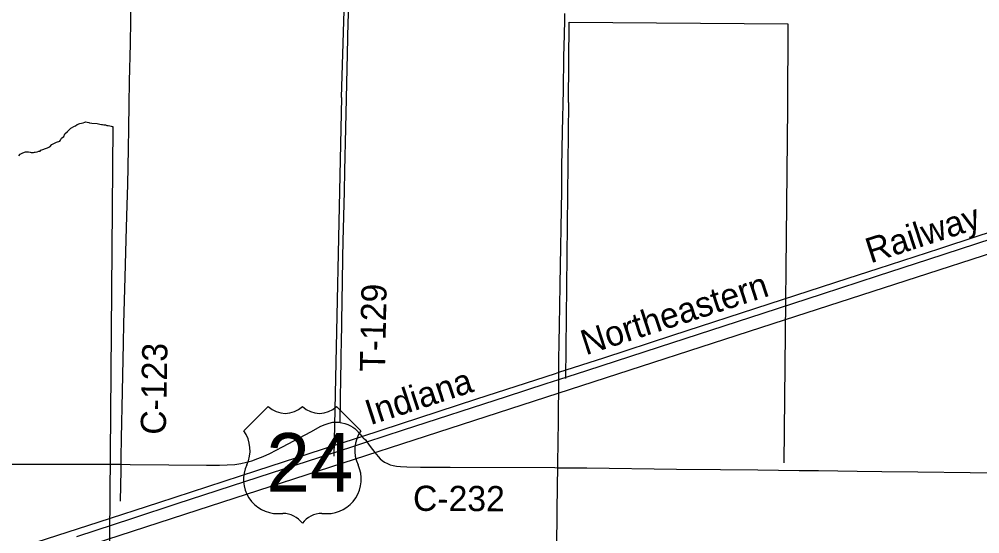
# Model space of a CAD drawing. Extents: x 2.1 to 73.9, y 4 to 26.
# Drawn here: x 44.489 to 45.571, y 21.257 to 21.837 of the extents above; entities that cross this region are included whole.
import ezdxf

# ---------------------------------------------------------------- set-up
doc = ezdxf.new("R2010")
doc.units = 0
for name, color, linetype in [('GM_X_County_Road', 7, 'Continuous'), ('GM_X_County_Road_Text', 7, 'Continuous'), ('GM_X_Minor_River', 7, 'Continuous'), ('GM_X_Rail_Line', 7, 'Continuous'), ('GM_X_Rail_Line_Text', 7, 'Continuous'), ('GM_X_Township_Road', 7, 'Continuous'), ('GM_X_Township_Road_Text', 7, 'Continuous'), ('GM_X_US_Location', 7, 'Continuous'), ('GM_X_US_Route', 7, 'Continuous'), ('GM_X_US_Shield', 7, 'Continuous')]:
    doc.layers.add(name, color=color, linetype=linetype)

msp = doc.modelspace()

# ---------------------------------------------------------------- linework, layer by layer
at = {"layer": 'GM_X_County_Road'}
for points in [[(44.6036, 21.3349), (44.6037, 21.3424), (44.604, 21.3642), (44.6051, 21.417), (44.6063, 21.4714), (44.6067, 21.4932), (44.6079, 21.546), (44.6088, 21.574), (44.6094, 21.602), (44.6102, 21.6269), (44.6109, 21.6502), (44.6119, 21.6906), (44.6122, 21.7139), (44.6125, 21.7404), (44.6131, 21.7668), (44.614, 21.8088), (44.6143, 21.8352), (44.6146, 21.8461), (44.6146, 21.8484)], [(45.0966, 21.4305), (45.0966, 21.432), (45.0967, 21.4386), (45.0968, 21.4538), (45.0971, 21.4709), (45.0975, 21.4926), (45.0978, 21.5128), (45.0981, 21.5377), (45.1, 21.6434), (45.1002, 21.6698), (45.101, 21.7102), (45.1018, 21.7568), (45.1025, 21.7941), (45.1031, 21.819), (45.1033, 21.836), (45.1033, 21.8392), (45.1033, 21.843)], [(45.0955, 21.331), (45.0956, 21.3357), (45.0963, 21.3839), (45.0964, 21.401), (45.0966, 21.4134), (45.0966, 21.4211), (45.0966, 21.4305)], [(44.6036, 21.3349), (44.6136, 21.3348), (44.6571, 21.3344), (44.6997, 21.3339), (44.7038, 21.3338), (44.7144, 21.3338), (44.7228, 21.3341), (44.7315, 21.3348), (44.7383, 21.3358), (44.7447, 21.3372), (44.7507, 21.3389), (44.7575, 21.3413), (44.7635, 21.3438), (44.7709, 21.3472), (44.7852, 21.3547), (44.8171, 21.3716), (44.8286, 21.3777), (44.8334, 21.3799), (44.8378, 21.3814), (44.842, 21.3822), (44.8456, 21.3824), (44.849, 21.3823), (44.8504, 21.3821)], [(44.8504, 21.3821), (44.8523, 21.3818), (44.8556, 21.381), (44.8591, 21.3798), (44.8621, 21.3784), (44.8647, 21.3768), (44.8669, 21.3751), (44.8684, 21.3736), (44.8727, 21.3687), (44.8738, 21.3675), (44.8748, 21.3663)], [(44.8748, 21.3663), (44.8763, 21.3648), (44.8787, 21.3624), (44.8802, 21.3605), (44.8805, 21.3601), (44.8842, 21.355), (44.8892, 21.3482), (44.893, 21.3436), (44.8954, 21.3411), (44.8978, 21.3391), (44.9004, 21.3373), (44.9035, 21.3357), (44.9067, 21.3344), (44.91, 21.3334), (44.9137, 21.3327), (44.9181, 21.3322), (44.9256, 21.3319), (44.9408, 21.3316), (44.9742, 21.3315), (45.0923, 21.3311), (45.0955, 21.331)], [(44.1039, 21.3377), (44.1441, 21.3374), (44.169, 21.3371), (44.183, 21.3371), (44.2094, 21.3368), (44.2778, 21.3362), (44.3073, 21.3361), (44.3851, 21.3355), (44.4146, 21.3354), (44.4581, 21.3352), (44.4799, 21.3352), (44.5561, 21.3351), (44.5996, 21.335), (44.6036, 21.3349)], [(45.0892, 20.8284), (45.0892, 20.8291), (45.0898, 20.8539), (45.0904, 20.8943), (45.0908, 20.9285), (45.0915, 20.9751), (45.0919, 21.014), (45.0926, 21.0917), (45.0928, 21.1212), (45.0932, 21.157), (45.094, 21.2129), (45.0944, 21.2409), (45.0948, 21.2813), (45.0951, 21.3108), (45.0955, 21.331)], [(45.0955, 21.331), (45.1281, 21.3308), (45.2291, 21.3295), (45.2789, 21.329), (45.3208, 21.3286), (45.3674, 21.3279), (45.3892, 21.3277), (45.4327, 21.3272), (45.4607, 21.3269), (45.5011, 21.3264), (45.5602, 21.3257), (45.6027, 21.3251)]]:
    msp.add_lwpolyline(points, dxfattribs=at)
at = {"layer": 'GM_X_Minor_River'}
for points in [[(44.8519, 21.7485), (44.8549, 21.8464)], [(45.1074, 21.7427), (45.1083, 21.8335), (45.3549, 21.8315), (45.3543, 21.737)], [(44.8519, 21.7485), (44.8432, 21.3439)], [(45.1074, 21.7427), (45.1041, 21.4317)], [(45.3543, 21.737), (45.3501, 21.3367)], [(44.4883, 21.6826), (44.4897, 21.6847), (44.4927, 21.6861), (44.4958, 21.6872), (44.4975, 21.6873), (44.4992, 21.6871), (44.5009, 21.6869), (44.5022, 21.6865), (44.5034, 21.6864), (44.5047, 21.6864), (44.5059, 21.6866), (44.5068, 21.6867), (44.5087, 21.6873), (44.5108, 21.6878), (44.5122, 21.6879), (44.513, 21.6891), (44.5204, 21.6917), (44.5221, 21.6923), (44.5231, 21.6928), (44.5255, 21.6954), (44.5306, 21.6982), (44.5343, 21.699), (44.5353, 21.7003), (44.5364, 21.7026), (44.5388, 21.7043), (44.5402, 21.7073), (44.5431, 21.7102), (44.5468, 21.7138), (44.551, 21.7161), (44.5522, 21.7163), (44.5539, 21.718), (44.557, 21.7192), (44.5606, 21.7199), (44.5625, 21.7206), (44.5637, 21.7208), (44.5654, 21.7206)], [(44.5654, 21.7206), (44.5671, 21.7203), (44.568, 21.7199), (44.5705, 21.7195), (44.5764, 21.719), (44.5781, 21.7186), (44.5796, 21.7183), (44.5813, 21.7181), (44.5826, 21.7179), (44.5839, 21.7177), (44.586, 21.7174), (44.5875, 21.717), (44.589, 21.7168), (44.5906, 21.7164), (44.5921, 21.7162), (44.5934, 21.7158), (44.5943, 21.7157)], [(44.5943, 21.7157), (44.5872, 20.8842)]]:
    msp.add_lwpolyline(points, dxfattribs=at)
at = {"layer": 'GM_X_Rail_Line'}
msp.add_lwpolyline([(41.9585, 20.391), (42.5865, 20.5973), (42.8825, 20.6932), (43.1284, 20.7728), (43.6337, 20.9392), (44.1637, 21.1124), (44.7042, 21.288), (45.0958, 21.4151), (45.351, 21.4977), (46.1224, 21.7471), (46.3771, 21.8296)], dxfattribs=at)
at = {"layer": 'GM_X_Township_Road'}
for points in [[(44.8504, 21.3821), (44.8504, 21.3871), (44.8506, 21.4049), (44.851, 21.4359), (44.8513, 21.4468), (44.8516, 21.4608), (44.8517, 21.4701), (44.8526, 21.5198), (44.853, 21.54), (44.8533, 21.5679), (44.8537, 21.5866), (44.8551, 21.6424), (44.8555, 21.6657), (44.8566, 21.7139), (44.8584, 21.7977), (44.8593, 21.8334), (44.8596, 21.8412), (44.8598, 21.8447)], [(44.6028, 21.2932), (44.6036, 21.3284), (44.6036, 21.3349)]]:
    msp.add_lwpolyline(points, dxfattribs=at)
at = {"layer": 'GM_X_US_Route'}
for points in [[(44.5079, 21.2469), (44.5788, 21.2699), (44.6459, 21.2917), (44.7565, 21.3277), (44.8454, 21.3567), (44.8748, 21.3663), (45.0044, 21.4085), (45.0931, 21.4374), (45.0967, 21.4386), (45.1475, 21.455), (45.2253, 21.4804), (45.3338, 21.5156), (45.4227, 21.5446), (45.4564, 21.5556), (45.5259, 21.5782), (45.5681, 21.592), (45.6107, 21.6058)], [(44.5535, 21.2536), (44.6165, 21.2741), (44.6667, 21.2905), (44.758, 21.3202), (44.8009, 21.3342), (44.8633, 21.3545), (44.8805, 21.3601), (44.9218, 21.3736), (45.0379, 21.4114), (45.0826, 21.4259), (45.0966, 21.4305), (45.1284, 21.4408), (45.21, 21.4673), (45.327, 21.5054), (45.3938, 21.5271), (45.4556, 21.5473), (45.5135, 21.5662), (45.6563, 21.6126)]]:
    msp.add_lwpolyline(points, dxfattribs=at)
at = {"layer": 'GM_X_US_Shield'}
for p, q in [((44.7693, 21.4002), (44.7418, 21.3727)), ((44.8737, 21.3727), (44.8462, 21.4002)), ((44.7803, 21.2793), (44.7858, 21.2793)), ((44.8297, 21.2793), (44.8352, 21.2793))]:
    msp.add_line(p, q, dxfattribs=at)
for centre, radius, start, end in [((44.7885, 21.4198), 0.0275, 225.573, 314.427), ((44.827, 21.4198), 0.0275, 225.573, 314.427), ((44.7103, 21.3507), 0.0385, 334.5471, 35.0009), ((44.9052, 21.3507), 0.0385, 144.9991, 205.4529), ((44.7798, 21.3178), 0.0385, 154.8319, 270.6383), ((44.8356, 21.3178), 0.0385, 269.3617, 25.1681), ((44.7858, 21.2519), 0.0275, 36.8699, 90), ((44.8297, 21.2519), 0.0275, 90, 143.1301)]:
    msp.add_arc(centre, radius, start, end, dxfattribs=at)

# ---------------------------------------------------------------- texts
at = {"layer": 'GM_X_County_Road_Text'}
for s, rotation, p in [('C-123', 88.8986, (44.6538, 21.368)), ('C-232', 359.7253, (44.9323, 21.2824))]:
    msp.add_text(s, height=0.02841, rotation=rotation, dxfattribs=at).set_placement(p)
at = {"layer": 'GM_X_Rail_Line_Text'}
for s, height, rotation, p in [('Railway', 0.02831, 17.9456, (45.4479, 21.5613)), ('Northeastern', 0.028314, 17.9613, (45.127, 21.4576)), ('Indiana', 0.02831, 18.0002, (44.8841, 21.3788))]:
    msp.add_text(s, height=height, rotation=rotation, dxfattribs=at).set_placement(p)
at = {"layer": 'GM_X_Township_Road_Text'}
msp.add_text('T-129', height=0.02841, rotation=88.8765, dxfattribs=at).set_placement((44.9008, 21.4389))
at = {"layer": 'GM_X_US_Location'}
for s in ['0', '/']:
    msp.add_text(s, height=0.0000947, dxfattribs=at).set_placement((44.8077, 21.3365))
msp.add_text('24', height=0.0000947, rotation=0, dxfattribs=at).set_placement((44.7882, 21.3169))
at = {"layer": 'GM_X_US_Shield'}
msp.add_text('24', height=0.06592, dxfattribs=at).set_placement((44.7671, 21.3041))

doc.saveas('drawing.dxf')
